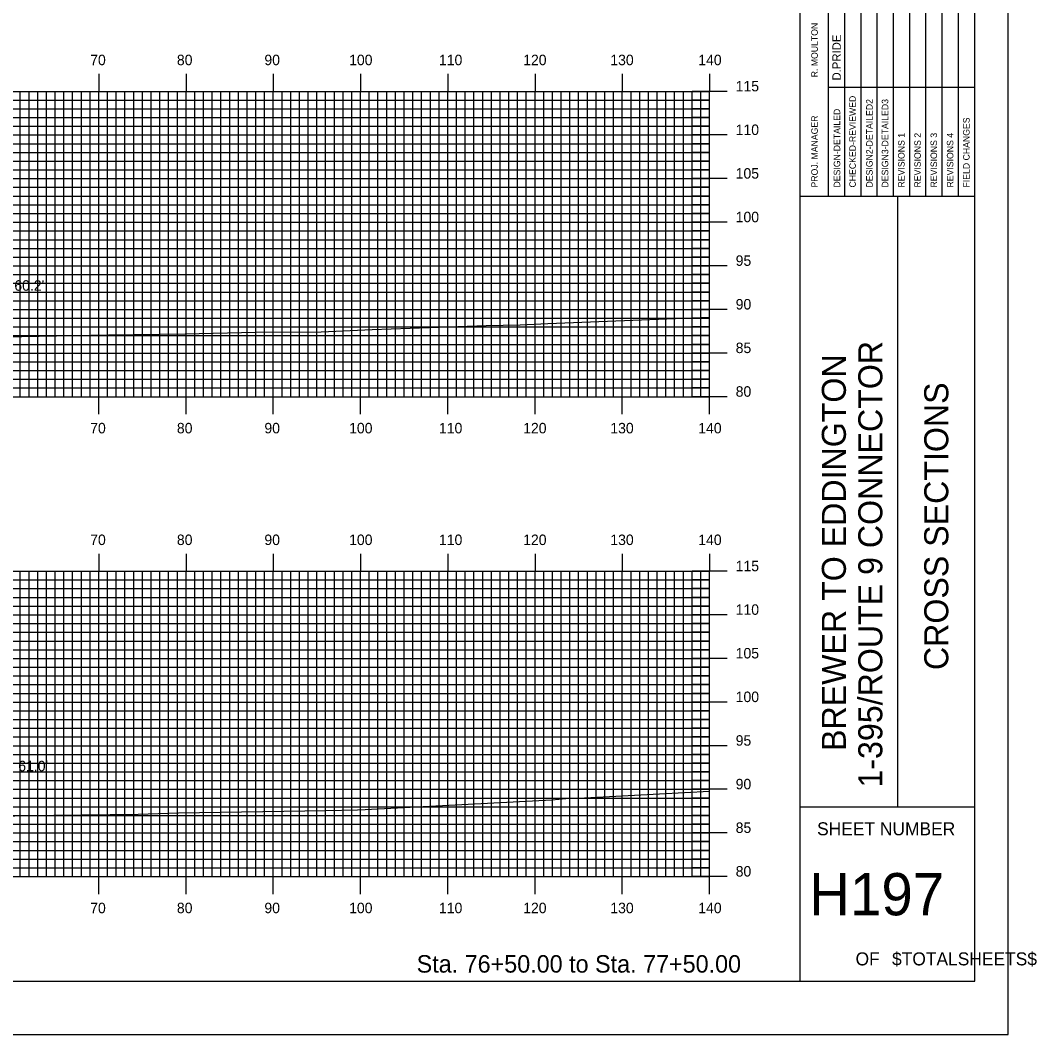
# Model space of a CAD drawing. Extents: x 1761791 to 1762134, y 442591 to 442811.
# Drawn here: x 1762017.8 to 1762134.2, y 442590.5 to 442706.8 of the extents above; entities that cross this region are included whole.
import ezdxf

# ---------------------------------------------------------------- set-up
doc = ezdxf.new("R2010")
doc.units = 0
for name, color, linetype in [('BORDER', 7, 'Continuous'), ('D_Text_Standard', 7, 'Continuous'), ('H_V ANNOTATION', 7, 'Continuous'), ('MAJOR', 7, 'Continuous'), ('MINOR', 7, 'Continuous'), ('PLOT BOUNDARY', 7, 'Continuous'), ('S_Roadway_Centerline', 7, 'Continuous')]:
    doc.layers.add(name, color=color, linetype=linetype)

msp = doc.modelspace()

# ---------------------------------------------------------------- linework, layer by layer
at = {"layer": 'BORDER'}
for p, q in [((1762107.15, 442596.67), (1762107.15, 442806.67)), ((1762107.15, 442686.67), (1762127.15, 442686.67)), ((1762118.34, 442616.67), (1762118.34, 442686.67)), ((1762107.15, 442616.67), (1762127.15, 442616.67))]:
    msp.add_line(p, q, dxfattribs=at)
msp.add_lwpolyline([(1761807.15, 442596.67), (1762127.15, 442596.67), (1762127.15, 442806.67), (1761807.15, 442806.67)], close=True, dxfattribs=at)
for points in [[(1762112.25, 442686.68), (1762112.25, 442721.67)], [(1762114.11, 442721.67), (1762114.11, 442686.68)], [(1762115.97, 442686.68), (1762115.97, 442721.67)], [(1762117.84, 442686.68), (1762117.84, 442721.67)], [(1762119.7, 442686.68), (1762119.7, 442721.67)], [(1762121.56, 442686.68), (1762121.56, 442721.67)], [(1762123.43, 442686.68), (1762123.43, 442721.67)], [(1762125.29, 442686.68), (1762125.29, 442721.67)], [(1762110.38, 442686.68), (1762110.38, 442720.26)], [(1762110.38, 442699.17), (1762127.15, 442699.17)]]:
    msp.add_lwpolyline(points, dxfattribs=at)
at = {"layer": 'MAJOR'}
for p, q in [((1762026.75, 442700.67), (1762026.75, 442698.67)), ((1762036.75, 442700.67), (1762036.75, 442698.67)), ((1762046.75, 442700.67), (1762046.75, 442698.67)), ((1762056.75, 442700.67), (1762056.75, 442698.67)), ((1762066.75, 442700.67), (1762066.75, 442698.67)), ((1762076.75, 442700.67), (1762076.75, 442698.67)), ((1762086.75, 442700.67), (1762086.75, 442698.67)), ((1762096.75, 442700.67), (1762096.75, 442698.67)), ((1761816.75, 442698.67), (1762096.75, 442698.67)), ((1761816.75, 442698.67), (1762096.75, 442698.67)), ((1762026.75, 442663.67), (1762026.75, 442698.67)), ((1762036.75, 442663.67), (1762036.75, 442698.67)), ((1762046.75, 442663.67), (1762046.75, 442698.67)), ((1762056.75, 442663.67), (1762056.75, 442698.67)), ((1762066.75, 442663.67), (1762066.75, 442698.67)), ((1762076.75, 442663.67), (1762076.75, 442698.67)), ((1762086.75, 442663.67), (1762086.75, 442698.67)), ((1762098.76, 442698.67), (1762094.75, 442698.67)), ((1762096.75, 442663.67), (1762096.75, 442698.67)), ((1762096.75, 442663.67), (1762096.75, 442698.67)), ((1761816.75, 442693.67), (1762096.75, 442693.67)), ((1762098.76, 442693.67), (1762094.75, 442693.67)), ((1761816.75, 442688.67), (1762096.75, 442688.67)), ((1762098.76, 442688.67), (1762094.75, 442688.67)), ((1761816.75, 442683.67), (1762096.75, 442683.67)), ((1762098.76, 442683.67), (1762094.75, 442683.67)), ((1761816.75, 442678.67), (1762096.75, 442678.67)), ((1762098.76, 442678.67), (1762094.75, 442678.67)), ((1761816.75, 442673.67), (1762096.75, 442673.67)), ((1762098.76, 442673.67), (1762094.75, 442673.67)), ((1761816.75, 442668.67), (1762096.75, 442668.67)), ((1762098.76, 442668.67), (1762094.75, 442668.67)), ((1761816.75, 442663.67), (1762096.75, 442663.67)), ((1761816.75, 442663.67), (1762096.75, 442663.67)), ((1762026.75, 442661.66), (1762026.75, 442663.67)), ((1762036.75, 442661.66), (1762036.75, 442663.67)), ((1762046.75, 442661.66), (1762046.75, 442663.67)), ((1762056.75, 442661.66), (1762056.75, 442663.67)), ((1762066.75, 442661.66), (1762066.75, 442663.67)), ((1762076.75, 442661.66), (1762076.75, 442663.67)), ((1762086.75, 442661.66), (1762086.75, 442663.67)), ((1762098.76, 442663.67), (1762094.75, 442663.67)), ((1762096.75, 442661.66), (1762096.75, 442663.67)), ((1762026.75, 442645.67), (1762026.75, 442643.67)), ((1762036.75, 442645.67), (1762036.75, 442643.67)), ((1762046.75, 442645.67), (1762046.75, 442643.67)), ((1762056.75, 442645.67), (1762056.75, 442643.67)), ((1762066.75, 442645.67), (1762066.75, 442643.67)), ((1762076.75, 442645.67), (1762076.75, 442643.67)), ((1762086.75, 442645.67), (1762086.75, 442643.67)), ((1762096.75, 442645.67), (1762096.75, 442643.67)), ((1761816.75, 442643.67), (1762096.75, 442643.67)), ((1761816.75, 442643.67), (1762096.75, 442643.67)), ((1762026.75, 442608.67), (1762026.75, 442643.67)), ((1762036.75, 442608.67), (1762036.75, 442643.67)), ((1762046.75, 442608.67), (1762046.75, 442643.67)), ((1762056.75, 442608.67), (1762056.75, 442643.67)), ((1762066.75, 442608.67), (1762066.75, 442643.67)), ((1762076.75, 442608.67), (1762076.75, 442643.67)), ((1762086.75, 442608.67), (1762086.75, 442643.67)), ((1762098.76, 442643.67), (1762094.75, 442643.67)), ((1762096.75, 442608.67), (1762096.75, 442643.67)), ((1762096.75, 442608.67), (1762096.75, 442643.67)), ((1761816.75, 442638.67), (1762096.75, 442638.67)), ((1762098.76, 442638.67), (1762094.75, 442638.67)), ((1761816.75, 442633.67), (1762096.75, 442633.67)), ((1762098.76, 442633.67), (1762094.75, 442633.67)), ((1761816.75, 442628.67), (1762096.75, 442628.67)), ((1762098.76, 442628.67), (1762094.75, 442628.67)), ((1761816.75, 442623.67), (1762096.75, 442623.67)), ((1762098.76, 442623.67), (1762094.75, 442623.67)), ((1761816.75, 442618.67), (1762096.75, 442618.67)), ((1762098.76, 442618.67), (1762094.75, 442618.67)), ((1761816.75, 442613.67), (1762096.75, 442613.67)), ((1762098.76, 442613.67), (1762094.75, 442613.67)), ((1761816.75, 442608.67), (1762096.75, 442608.67)), ((1761816.75, 442608.67), (1762096.75, 442608.67)), ((1762026.75, 442606.66), (1762026.75, 442608.67)), ((1762036.75, 442606.66), (1762036.75, 442608.67)), ((1762046.75, 442606.66), (1762046.75, 442608.67)), ((1762056.75, 442606.66), (1762056.75, 442608.67)), ((1762066.75, 442606.66), (1762066.75, 442608.67)), ((1762076.75, 442606.66), (1762076.75, 442608.67)), ((1762086.75, 442606.66), (1762086.75, 442608.67)), ((1762098.76, 442608.67), (1762094.75, 442608.67)), ((1762096.75, 442606.66), (1762096.75, 442608.67))]:
    msp.add_line(p, q, dxfattribs=at)
at = {"layer": 'MINOR'}
for p, q in [((1762017.75, 442663.67), (1762017.75, 442698.67)), ((1762018.75, 442663.67), (1762018.75, 442698.67)), ((1762019.75, 442663.67), (1762019.75, 442698.67)), ((1762020.75, 442663.67), (1762020.75, 442698.67)), ((1762021.75, 442663.67), (1762021.75, 442698.67)), ((1762022.75, 442663.67), (1762022.75, 442698.67)), ((1762023.75, 442663.67), (1762023.75, 442698.67)), ((1762024.75, 442663.67), (1762024.75, 442698.67)), ((1762025.75, 442663.67), (1762025.75, 442698.67)), ((1762027.75, 442663.67), (1762027.75, 442698.67)), ((1762028.75, 442663.67), (1762028.75, 442698.67)), ((1762029.75, 442663.67), (1762029.75, 442698.67)), ((1762030.75, 442663.67), (1762030.75, 442698.67)), ((1762031.75, 442663.67), (1762031.75, 442698.67)), ((1762032.75, 442663.67), (1762032.75, 442698.67)), ((1762033.75, 442663.67), (1762033.75, 442698.67)), ((1762034.75, 442663.67), (1762034.75, 442698.67)), ((1762035.75, 442663.67), (1762035.75, 442698.67)), ((1762037.75, 442663.67), (1762037.75, 442698.67)), ((1762038.75, 442663.67), (1762038.75, 442698.67)), ((1762039.75, 442663.67), (1762039.75, 442698.67)), ((1762040.75, 442663.67), (1762040.75, 442698.67)), ((1762041.75, 442663.67), (1762041.75, 442698.67)), ((1762042.75, 442663.67), (1762042.75, 442698.67)), ((1762043.75, 442663.67), (1762043.75, 442698.67)), ((1762044.75, 442663.67), (1762044.75, 442698.67)), ((1762045.75, 442663.67), (1762045.75, 442698.67)), ((1762047.75, 442663.67), (1762047.75, 442698.67)), ((1762048.75, 442663.67), (1762048.75, 442698.67)), ((1762049.75, 442663.67), (1762049.75, 442698.67)), ((1762050.75, 442663.67), (1762050.75, 442698.67)), ((1762051.75, 442663.67), (1762051.75, 442698.67)), ((1762052.75, 442663.67), (1762052.75, 442698.67)), ((1762053.75, 442663.67), (1762053.75, 442698.67)), ((1762054.75, 442663.67), (1762054.75, 442698.67)), ((1762055.75, 442663.67), (1762055.75, 442698.67)), ((1762057.75, 442663.67), (1762057.75, 442698.67)), ((1762058.75, 442663.67), (1762058.75, 442698.67)), ((1762059.75, 442663.67), (1762059.75, 442698.67)), ((1762060.75, 442663.67), (1762060.75, 442698.67)), ((1762061.75, 442663.67), (1762061.75, 442698.67)), ((1762062.75, 442663.67), (1762062.75, 442698.67)), ((1762063.75, 442663.67), (1762063.75, 442698.67)), ((1762064.75, 442663.67), (1762064.75, 442698.67)), ((1762065.75, 442663.67), (1762065.75, 442698.67)), ((1762067.75, 442663.67), (1762067.75, 442698.67)), ((1762068.75, 442663.67), (1762068.75, 442698.67)), ((1762069.75, 442663.67), (1762069.75, 442698.67)), ((1762070.75, 442663.67), (1762070.75, 442698.67)), ((1762071.75, 442663.67), (1762071.75, 442698.67)), ((1762072.75, 442663.67), (1762072.75, 442698.67)), ((1762073.75, 442663.67), (1762073.75, 442698.67)), ((1762074.75, 442663.67), (1762074.75, 442698.67)), ((1762075.75, 442663.67), (1762075.75, 442698.67)), ((1762077.75, 442663.67), (1762077.75, 442698.67)), ((1762078.75, 442663.67), (1762078.75, 442698.67)), ((1762079.75, 442663.67), (1762079.75, 442698.67)), ((1762080.75, 442663.67), (1762080.75, 442698.67)), ((1762081.75, 442663.67), (1762081.75, 442698.67)), ((1762082.75, 442663.67), (1762082.75, 442698.67)), ((1762083.75, 442663.67), (1762083.75, 442698.67)), ((1762084.75, 442663.67), (1762084.75, 442698.67)), ((1762085.75, 442663.67), (1762085.75, 442698.67)), ((1762087.75, 442663.67), (1762087.75, 442698.67)), ((1762088.75, 442663.67), (1762088.75, 442698.67)), ((1762089.75, 442663.67), (1762089.75, 442698.67)), ((1762090.75, 442663.67), (1762090.75, 442698.67)), ((1762091.75, 442663.67), (1762091.75, 442698.67)), ((1762092.75, 442663.67), (1762092.75, 442698.67)), ((1762093.75, 442663.67), (1762093.75, 442698.67)), ((1762094.75, 442663.67), (1762094.75, 442698.67)), ((1762095.75, 442663.67), (1762095.75, 442698.67)), ((1761816.75, 442697.67), (1762096.75, 442697.67)), ((1762096.75, 442697.67), (1762094.75, 442697.67)), ((1761816.75, 442696.67), (1762096.75, 442696.67)), ((1762096.75, 442696.67), (1762094.75, 442696.67)), ((1761816.75, 442695.67), (1762096.75, 442695.67)), ((1761816.75, 442694.67), (1762096.75, 442694.67)), ((1762096.75, 442695.67), (1762094.75, 442695.67)), ((1762096.75, 442694.67), (1762094.75, 442694.67)), ((1761816.75, 442692.67), (1762096.75, 442692.67)), ((1762096.75, 442692.67), (1762094.75, 442692.67)), ((1761816.75, 442691.67), (1762096.75, 442691.67)), ((1762096.75, 442691.67), (1762094.75, 442691.67)), ((1761816.75, 442690.67), (1762096.75, 442690.67)), ((1762096.75, 442690.67), (1762094.75, 442690.67)), ((1761816.75, 442689.67), (1762096.75, 442689.67)), ((1762096.75, 442689.67), (1762094.75, 442689.67)), ((1761816.75, 442687.67), (1762096.75, 442687.67)), ((1762096.75, 442687.67), (1762094.75, 442687.67)), ((1761816.75, 442686.67), (1762096.75, 442686.67)), ((1762096.75, 442686.67), (1762094.75, 442686.67)), ((1761816.75, 442685.67), (1762096.75, 442685.67)), ((1762096.75, 442685.67), (1762094.75, 442685.67)), ((1761816.75, 442684.67), (1762096.75, 442684.67)), ((1762096.75, 442684.67), (1762094.75, 442684.67)), ((1761816.75, 442682.67), (1762096.75, 442682.67)), ((1762096.75, 442682.67), (1762094.75, 442682.67)), ((1761816.75, 442681.67), (1762096.75, 442681.67)), ((1761816.75, 442680.67), (1762096.75, 442680.67)), ((1762096.75, 442681.67), (1762094.75, 442681.67)), ((1762096.75, 442680.67), (1762094.75, 442680.67)), ((1761816.75, 442679.67), (1762096.75, 442679.67)), ((1762096.75, 442679.67), (1762094.75, 442679.67)), ((1761816.75, 442677.67), (1762096.75, 442677.67)), ((1762096.75, 442677.67), (1762094.75, 442677.67)), ((1761816.75, 442676.67), (1762096.75, 442676.67)), ((1762096.75, 442676.67), (1762094.75, 442676.67)), ((1761816.75, 442675.67), (1762096.75, 442675.67)), ((1762096.75, 442675.67), (1762094.75, 442675.67)), ((1761816.75, 442674.67), (1762096.75, 442674.67)), ((1762096.75, 442674.67), (1762094.75, 442674.67)), ((1761816.75, 442672.67), (1762096.75, 442672.67)), ((1762096.75, 442672.67), (1762094.75, 442672.67)), ((1761816.75, 442671.67), (1762096.75, 442671.67)), ((1762096.75, 442671.67), (1762094.75, 442671.67)), ((1761816.75, 442670.67), (1762096.75, 442670.67)), ((1762096.75, 442670.67), (1762094.75, 442670.67)), ((1761816.75, 442669.67), (1762096.75, 442669.67)), ((1762096.75, 442669.67), (1762094.75, 442669.67)), ((1761816.75, 442667.67), (1762096.75, 442667.67)), ((1761816.75, 442666.67), (1762096.75, 442666.67)), ((1762096.75, 442667.67), (1762094.75, 442667.67)), ((1762096.75, 442666.67), (1762094.75, 442666.67)), ((1761816.75, 442665.67), (1762096.75, 442665.67)), ((1762096.75, 442665.67), (1762094.75, 442665.67)), ((1761816.75, 442664.67), (1762096.75, 442664.67)), ((1762096.75, 442664.67), (1762094.75, 442664.67)), ((1762017.75, 442608.67), (1762017.75, 442643.67)), ((1762018.75, 442608.67), (1762018.75, 442643.67)), ((1762019.75, 442608.67), (1762019.75, 442643.67)), ((1762020.75, 442608.67), (1762020.75, 442643.67)), ((1762021.75, 442608.67), (1762021.75, 442643.67)), ((1762022.75, 442608.67), (1762022.75, 442643.67)), ((1762023.75, 442608.67), (1762023.75, 442643.67)), ((1762024.75, 442608.67), (1762024.75, 442643.67)), ((1762025.75, 442608.67), (1762025.75, 442643.67)), ((1762027.75, 442608.67), (1762027.75, 442643.67)), ((1762028.75, 442608.67), (1762028.75, 442643.67)), ((1762029.75, 442608.67), (1762029.75, 442643.67)), ((1762030.75, 442608.67), (1762030.75, 442643.67)), ((1762031.75, 442608.67), (1762031.75, 442643.67)), ((1762032.75, 442608.67), (1762032.75, 442643.67)), ((1762033.75, 442608.67), (1762033.75, 442643.67)), ((1762034.75, 442608.67), (1762034.75, 442643.67)), ((1762035.75, 442608.67), (1762035.75, 442643.67)), ((1762037.75, 442608.67), (1762037.75, 442643.67)), ((1762038.75, 442608.67), (1762038.75, 442643.67)), ((1762039.75, 442608.67), (1762039.75, 442643.67)), ((1762040.75, 442608.67), (1762040.75, 442643.67)), ((1762041.75, 442608.67), (1762041.75, 442643.67)), ((1762042.75, 442608.67), (1762042.75, 442643.67)), ((1762043.75, 442608.67), (1762043.75, 442643.67)), ((1762044.75, 442608.67), (1762044.75, 442643.67)), ((1762045.75, 442608.67), (1762045.75, 442643.67)), ((1762047.75, 442608.67), (1762047.75, 442643.67)), ((1762048.75, 442608.67), (1762048.75, 442643.67)), ((1762049.75, 442608.67), (1762049.75, 442643.67)), ((1762050.75, 442608.67), (1762050.75, 442643.67)), ((1762051.75, 442608.67), (1762051.75, 442643.67)), ((1762052.75, 442608.67), (1762052.75, 442643.67)), ((1762053.75, 442608.67), (1762053.75, 442643.67)), ((1762054.75, 442608.67), (1762054.75, 442643.67)), ((1762055.75, 442608.67), (1762055.75, 442643.67)), ((1762057.75, 442608.67), (1762057.75, 442643.67)), ((1762058.75, 442608.67), (1762058.75, 442643.67)), ((1762059.75, 442608.67), (1762059.75, 442643.67)), ((1762060.75, 442608.67), (1762060.75, 442643.67)), ((1762061.75, 442608.67), (1762061.75, 442643.67)), ((1762062.75, 442608.67), (1762062.75, 442643.67)), ((1762063.75, 442608.67), (1762063.75, 442643.67)), ((1762064.75, 442608.67), (1762064.75, 442643.67)), ((1762065.75, 442608.67), (1762065.75, 442643.67)), ((1762067.75, 442608.67), (1762067.75, 442643.67)), ((1762068.75, 442608.67), (1762068.75, 442643.67)), ((1762069.75, 442608.67), (1762069.75, 442643.67)), ((1762070.75, 442608.67), (1762070.75, 442643.67)), ((1762071.75, 442608.67), (1762071.75, 442643.67)), ((1762072.75, 442608.67), (1762072.75, 442643.67)), ((1762073.75, 442608.67), (1762073.75, 442643.67)), ((1762074.75, 442608.67), (1762074.75, 442643.67)), ((1762075.75, 442608.67), (1762075.75, 442643.67)), ((1762077.75, 442608.67), (1762077.75, 442643.67)), ((1762078.75, 442608.67), (1762078.75, 442643.67)), ((1762079.75, 442608.67), (1762079.75, 442643.67)), ((1762080.75, 442608.67), (1762080.75, 442643.67)), ((1762081.75, 442608.67), (1762081.75, 442643.67)), ((1762082.75, 442608.67), (1762082.75, 442643.67)), ((1762083.75, 442608.67), (1762083.75, 442643.67)), ((1762084.75, 442608.67), (1762084.75, 442643.67)), ((1762085.75, 442608.67), (1762085.75, 442643.67)), ((1762087.75, 442608.67), (1762087.75, 442643.67)), ((1762088.75, 442608.67), (1762088.75, 442643.67)), ((1762089.75, 442608.67), (1762089.75, 442643.67)), ((1762090.75, 442608.67), (1762090.75, 442643.67)), ((1762091.75, 442608.67), (1762091.75, 442643.67)), ((1762092.75, 442608.67), (1762092.75, 442643.67)), ((1762093.75, 442608.67), (1762093.75, 442643.67)), ((1762094.75, 442608.67), (1762094.75, 442643.67)), ((1762095.75, 442608.67), (1762095.75, 442643.67)), ((1761816.75, 442642.67), (1762096.75, 442642.67)), ((1762096.75, 442642.67), (1762094.75, 442642.67)), ((1761816.75, 442641.67), (1762096.75, 442641.67)), ((1762096.75, 442641.67), (1762094.75, 442641.67)), ((1761816.75, 442640.67), (1762096.75, 442640.67)), ((1762096.75, 442640.67), (1762094.75, 442640.67)), ((1761816.75, 442639.67), (1762096.75, 442639.67)), ((1762096.75, 442639.67), (1762094.75, 442639.67)), ((1761816.75, 442637.67), (1762096.75, 442637.67)), ((1762096.75, 442637.67), (1762094.75, 442637.67)), ((1761816.75, 442636.67), (1762096.75, 442636.67)), ((1762096.75, 442636.67), (1762094.75, 442636.67)), ((1761816.75, 442635.67), (1762096.75, 442635.67)), ((1762096.75, 442635.67), (1762094.75, 442635.67)), ((1761816.75, 442634.67), (1762096.75, 442634.67)), ((1762096.75, 442634.67), (1762094.75, 442634.67)), ((1761816.75, 442632.67), (1762096.75, 442632.67)), ((1762096.75, 442632.67), (1762094.75, 442632.67)), ((1761816.75, 442631.67), (1762096.75, 442631.67)), ((1761816.75, 442630.67), (1762096.75, 442630.67)), ((1762096.75, 442631.67), (1762094.75, 442631.67)), ((1762096.75, 442630.67), (1762094.75, 442630.67)), ((1761816.75, 442629.67), (1762096.75, 442629.67)), ((1762096.75, 442629.67), (1762094.75, 442629.67)), ((1761816.75, 442627.67), (1762096.75, 442627.67)), ((1762096.75, 442627.67), (1762094.75, 442627.67)), ((1761816.75, 442626.67), (1762096.75, 442626.67)), ((1762096.75, 442626.67), (1762094.75, 442626.67)), ((1761816.75, 442625.67), (1762096.75, 442625.67)), ((1762096.75, 442625.67), (1762094.75, 442625.67)), ((1761816.75, 442624.67), (1762096.75, 442624.67)), ((1762096.75, 442624.67), (1762094.75, 442624.67)), ((1761816.75, 442622.67), (1762096.75, 442622.67)), ((1762096.75, 442622.67), (1762094.75, 442622.67)), ((1761816.75, 442621.67), (1762096.75, 442621.67)), ((1762096.75, 442621.67), (1762094.75, 442621.67)), ((1761816.75, 442620.67), (1762096.75, 442620.67)), ((1762096.75, 442620.67), (1762094.75, 442620.67)), ((1761816.75, 442619.67), (1762096.75, 442619.67)), ((1762096.75, 442619.67), (1762094.75, 442619.67)), ((1761816.75, 442617.67), (1762096.75, 442617.67)), ((1761816.75, 442616.67), (1762096.75, 442616.67)), ((1762096.75, 442617.67), (1762094.75, 442617.67)), ((1762096.75, 442616.67), (1762094.75, 442616.67)), ((1761816.75, 442615.67), (1762096.75, 442615.67)), ((1762096.75, 442615.67), (1762094.75, 442615.67)), ((1761816.75, 442614.67), (1762096.75, 442614.67)), ((1762096.75, 442614.67), (1762094.75, 442614.67)), ((1761816.75, 442612.67), (1762096.75, 442612.67)), ((1762096.75, 442612.67), (1762094.75, 442612.67)), ((1761816.75, 442611.67), (1762096.75, 442611.67)), ((1762096.75, 442611.67), (1762094.75, 442611.67)), ((1761816.75, 442610.67), (1762096.75, 442610.67)), ((1761816.75, 442609.67), (1762096.75, 442609.67)), ((1762096.75, 442610.67), (1762094.75, 442610.67)), ((1762096.75, 442609.67), (1762094.75, 442609.67))]:
    msp.add_line(p, q, dxfattribs=at)
at = {"layer": 'PLOT BOUNDARY'}
msp.add_lwpolyline([(1761790.97, 442590.55), (1762130.97, 442590.55), (1762130.97, 442810.55), (1761790.97, 442810.55)], close=True, dxfattribs=at)
at = {"layer": 'S_Roadway_Centerline'}
for points in [[(1762015.95, 442670.54), (1762027.87, 442670.75), (1762036.65, 442670.86), (1762044.7, 442671.07), (1762052.22, 442671.1), (1762058.09, 442671.38), (1762071.14, 442671.82), (1762075.06, 442671.9), (1762078.21, 442672.07), (1762096.75, 442672.78)], [(1762014.87, 442615.6), (1762021.59, 442615.71), (1762031.26, 442615.84), (1762035.9, 442615.96), (1762052.79, 442616.25), (1762056.39, 442616.32), (1762057.29, 442616.35), (1762078.67, 442617.48), (1762080.29, 442617.6), (1762082.42, 442617.7), (1762096.75, 442618.44)]]:
    msp.add_lwpolyline(points, dxfattribs=at)

# ---------------------------------------------------------------- texts
at = {"layer": 'BORDER'}
for s, height, p in [('R. MOULTON', 0.745, (1762109.16, 442700.28)), ('D.PRIDE', 0.969, (1762111.8, 442699.92)), ('CHECKED-REVIEWED', 0.7455, (1762113.52, 442687.65)), ('DESIGN2-DETAILED2', 0.7455, (1762115.45, 442687.65)), ('DESIGN3-DETAILED3', 0.7455, (1762117.24, 442687.65)), ('PROJ. MANAGER', 0.7455, (1762109.16, 442687.65)), ('DESIGN-DETAILED', 0.7455, (1762111.73, 442687.65)), ('FIELD CHANGES', 0.7455, (1762126.56, 442687.65)), ('REVISIONS 1', 0.7455, (1762119.11, 442687.65)), ('REVISIONS 2', 0.7455, (1762120.97, 442687.65)), ('REVISIONS 3', 0.7455, (1762122.83, 442687.65)), ('REVISIONS 4', 0.7455, (1762124.7, 442687.65)), ('1-395/ROUTE 9 CONNECTOR', 2.7557, (1762116.56, 442618.87)), ('BREWER TO EDDINGTON', 2.7557, (1762112.38, 442623.07)), ('CROSS SECTIONS', 2.7557, (1762124.12, 442632.34))]:
    msp.add_text(s, height=height, rotation=90, dxfattribs=at).set_placement(p)
for s, height, p in [('SHEET NUMBER', 1.4905, (1762109.08, 442613.4)), ('H197', 4.839, (1762108.18, 442604.23)), ('OF', 1.491, (1762113.49, 442598.49)), ('$TOTALSHEETS$', 1.4905, (1762117.67, 442598.49))]:
    msp.add_text(s, height=height, dxfattribs=at).set_placement(p)
at = {"layer": 'D_Text_Standard'}
for s, p in [("60.2'", (1762017.07, 442675.82)), ("61.0'", (1762017.52, 442620.74))]:
    msp.add_text(s, height=1.2, dxfattribs=at).set_placement(p)
at = {"layer": 'H_V ANNOTATION'}
for s, height, p in [('70', 1.2, (1762025.76, 442701.67)), ('80', 1.2, (1762035.7, 442701.67)), ('90', 1.2, (1762045.73, 442701.67)), ('100', 1.2, (1762055.44, 442701.67)), ('110', 1.2, (1762065.74, 442701.67)), ('120', 1.2, (1762075.39, 442701.67)), ('130', 1.2, (1762085.38, 442701.67)), ('140', 1.2, (1762095.46, 442701.67)), ('115', 1.2, (1762099.75, 442698.67)), ('110', 1.2, (1762099.75, 442693.67)), ('105', 1.2, (1762099.75, 442688.67)), ('100', 1.2, (1762099.75, 442683.67)), ('95', 1.2, (1762099.75, 442678.67)), ('90', 1.2, (1762099.75, 442673.67)), ('85', 1.2, (1762099.75, 442668.67)), ('80', 1.2, (1762099.75, 442663.67)), ('70', 1.2, (1762025.76, 442659.47)), ('80', 1.2, (1762035.7, 442659.47)), ('90', 1.2, (1762045.73, 442659.47)), ('100', 1.2, (1762055.44, 442659.47)), ('110', 1.2, (1762065.74, 442659.47)), ('120', 1.2, (1762075.39, 442659.47)), ('130', 1.2, (1762085.38, 442659.47)), ('140', 1.2, (1762095.46, 442659.47)), ('70', 1.2, (1762025.76, 442646.67)), ('80', 1.2, (1762035.7, 442646.67)), ('90', 1.2, (1762045.73, 442646.67)), ('100', 1.2, (1762055.44, 442646.67)), ('110', 1.2, (1762065.74, 442646.67)), ('120', 1.2, (1762075.39, 442646.67)), ('130', 1.2, (1762085.38, 442646.67)), ('140', 1.2, (1762095.46, 442646.67)), ('115', 1.2, (1762099.75, 442643.67)), ('110', 1.2, (1762099.75, 442638.67)), ('105', 1.2, (1762099.75, 442633.67)), ('100', 1.2, (1762099.75, 442628.67)), ('95', 1.2, (1762099.75, 442623.67)), ('90', 1.2, (1762099.75, 442618.67)), ('85', 1.2, (1762099.75, 442613.67)), ('80', 1.2, (1762099.75, 442608.67)), ('70', 1.2, (1762025.76, 442604.47)), ('80', 1.2, (1762035.7, 442604.47)), ('90', 1.2, (1762045.73, 442604.47)), ('100', 1.2, (1762055.44, 442604.47)), ('110', 1.2, (1762065.74, 442604.47)), ('120', 1.2, (1762075.39, 442604.47)), ('130', 1.2, (1762085.38, 442604.47)), ('140', 1.2, (1762095.46, 442604.47)), ('Sta. 76+50.00 to Sta. 77+50.00', 2.0004, (1762063.18, 442597.66))]:
    msp.add_text(s, height=height, dxfattribs=at).set_placement(p)

doc.saveas('drawing.dxf')
